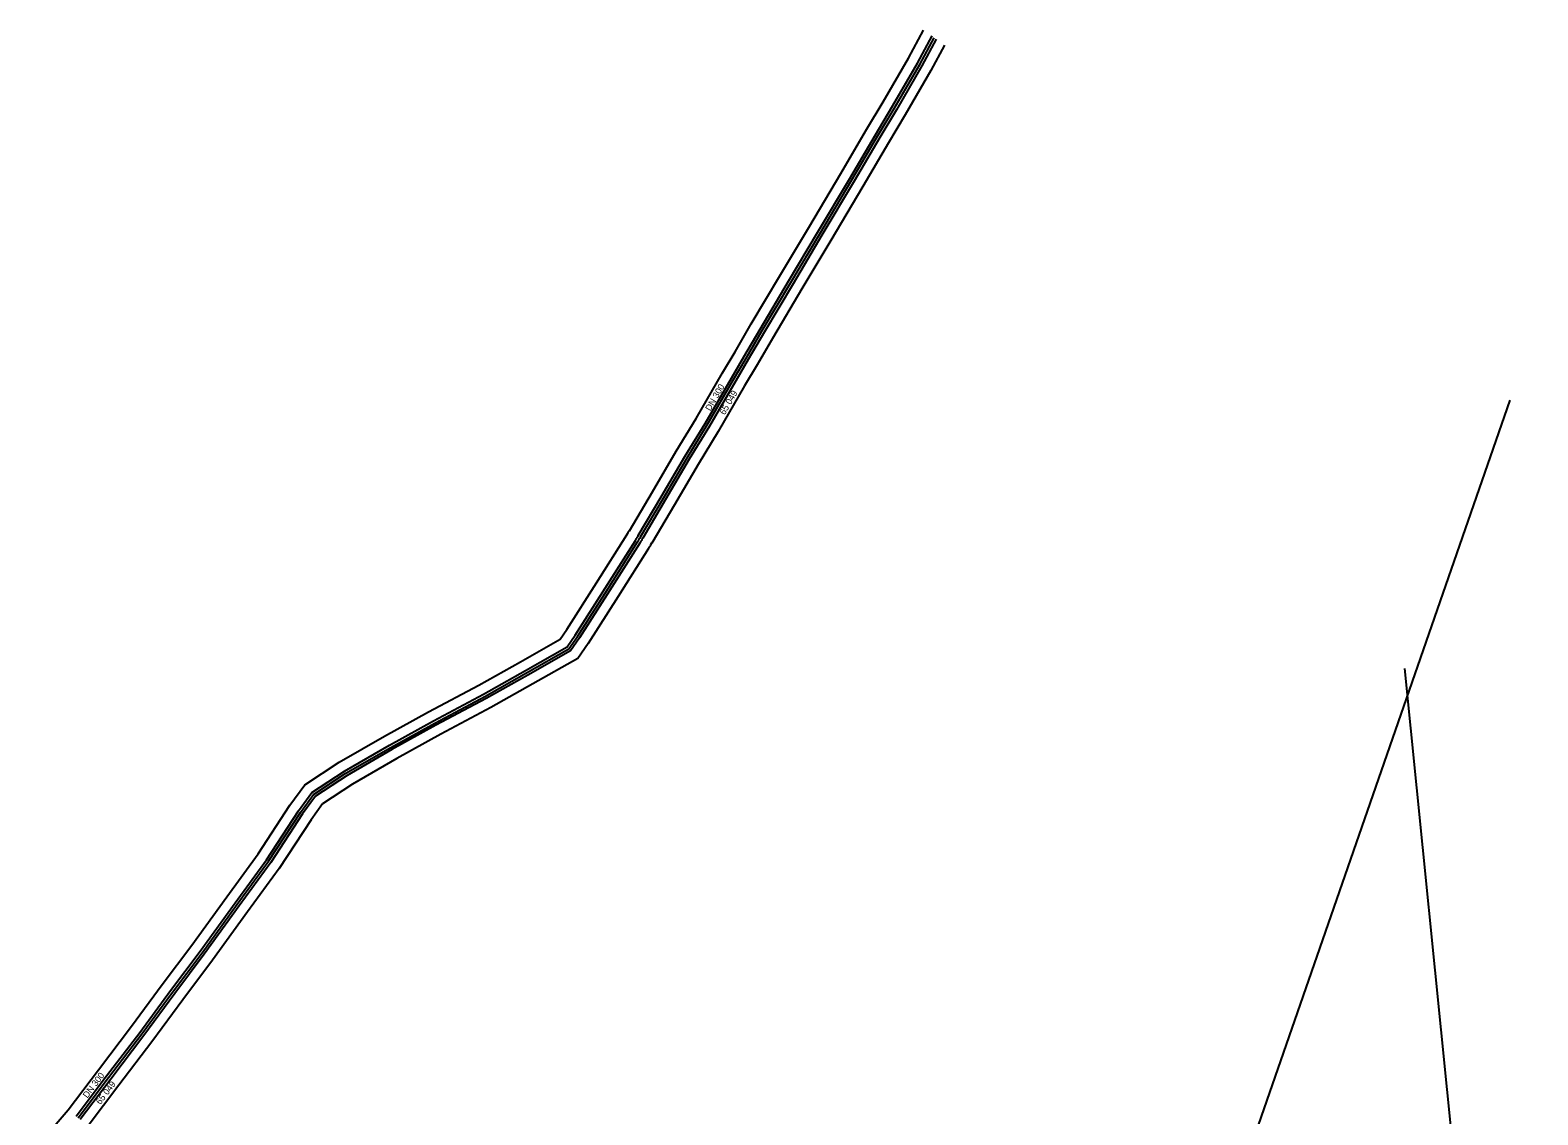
# Model space of a CAD drawing. Extents: x -546883 to -534032, y -1096714 to -1090569.
# Drawn here: x -542860 to -540504, y -1092586 to -1090891 of the extents above; entities that cross this region are included whole.
import ezdxf

# ---------------------------------------------------------------- set-up
doc = ezdxf.new("R2010")
doc.units = 0
for name, color, linetype in [('Vrstva 22', 7, 'Continuous'), ('Vrstva 26', 7, 'Continuous'), ('Vrstva 3', 7, 'Continuous'), ('Vrstva 8', 7, 'Continuous')]:
    doc.layers.add(name, color=color, linetype=linetype)

msp = doc.modelspace()

# ---------------------------------------------------------------- linework, layer by layer
at = {"layer": 'Vrstva 22'}
for p, q in [((-541554.5, -1094369.3), (-540547.1, -1091469.5)), ((-540503.9, -1093950.2), (-540711.5, -1091888.4))]:
    msp.add_line(p, q, dxfattribs=at)
at = {"layer": 'Vrstva 26'}
msp.add_lwpolyline([(-542785.2, -1092590.2), (-542737.4, -1092527.2), (-542685.7, -1092459.3), (-542637.4, -1092393.8), (-542591.2, -1092332.3), (-542536.4, -1092256.6), (-542487.4, -1092189.3), (-542437.5, -1092113.2), (-542417, -1092085.1), (-542366.6, -1092052), (-542296.6, -1092011.6), (-542227.8, -1091973.6), (-542149.5, -1091932), (-542084.2, -1091895.2), (-542018.2, -1091857.7), (-542004.8, -1091838.4), (-541957.9, -1091765.3), (-541910.7, -1091690.5), (-541908.9, -1091687.5), (-541908.6, -1091687), (-541908.2, -1091686.3), (-541907.8, -1091685.6), (-541907.4, -1091685.1), (-541906.2, -1091683.1), (-541906.1, -1091682.8), (-541870.5, -1091622.5), (-541833.4, -1091559.4), (-541801.9, -1091508.1), (-541760.8, -1091437), (-541741.3, -1091403.8), (-541715.9, -1091360.5), (-541671.2, -1091285.4), (-541626.1, -1091209.7), (-541575.8, -1091125.4), (-541535.8, -1091057), (-541509.7, -1091013.7), (-541469.9, -1090944.9), (-541447.3, -1090903.2)], dxfattribs=at)
at = {"layer": 'Vrstva 3'}
for points in [[(-542860, -1092647.2), (-542800.8, -1092577.6), (-542753.3, -1092515.1), (-542701.7, -1092447.3), (-542653.5, -1092381.8), (-542607.3, -1092320.4), (-542552.6, -1092244.9), (-542503.8, -1092178), (-542454, -1092101.9), (-542431, -1092070.4), (-542377.1, -1092034.9), (-542306.4, -1091994.1), (-542237.3, -1091956), (-542159.1, -1091914.5), (-542094, -1091877.8), (-542032, -1091842.5), (-542021.4, -1091827.3), (-541974.8, -1091754.5), (-541927.7, -1091679.9), (-541926, -1091677.1), (-541925.7, -1091676.7), (-541925.3, -1091675.9), (-541924.8, -1091675.2), (-541924.5, -1091674.7), (-541923.7, -1091673.4), (-541923.6, -1091673.2), (-541887.7, -1091612.4), (-541850.6, -1091549.1), (-541819, -1091497.8), (-541778, -1091426.9), (-541758.5, -1091393.7), (-541733.1, -1091350.3), (-541688.4, -1091275.2), (-541643.3, -1091199.4), (-541593, -1091115.2), (-541553, -1091046.8), (-541526.9, -1091003.6), (-541487.4, -1090935.1), (-541463.7, -1090891.5)], [(-541430.9, -1090914.9), (-541452.5, -1090954.7), (-541492.5, -1091023.9), (-541518.6, -1091067.2), (-541558.6, -1091135.5), (-541609, -1091219.9), (-541654.1, -1091295.6), (-541698.6, -1091370.6), (-541724, -1091413.9), (-541743.5, -1091447.1), (-541784.7, -1091518.3), (-541816.3, -1091569.7), (-541853.2, -1091632.7), (-541888.6, -1091692.5), (-541888.8, -1091692.9), (-541890.4, -1091695.5), (-541890.7, -1091696), (-541891.1, -1091696.7), (-541891.4, -1091697.3), (-541891.8, -1091697.9), (-541893.8, -1091701.1), (-541941, -1091776), (-541988.1, -1091849.5), (-542004.4, -1091872.8), (-542074.3, -1091912.6), (-542139.9, -1091949.5), (-542218.2, -1091991.2), (-542286.8, -1092029), (-542356.1, -1092069), (-542403, -1092099.9), (-542421.1, -1092124.6), (-542470.9, -1092200.7), (-542520.2, -1092268.4), (-542575.1, -1092344.2), (-542621.4, -1092405.7), (-542669.7, -1092471.3), (-542721.4, -1092539.3), (-542769.6, -1092602.7)]]:
    msp.add_lwpolyline(points, dxfattribs=at)
at = {"layer": 'Vrstva 8'}
for points in [[(-542788.3, -1092587.7), (-542740.5, -1092524.7), (-542688.9, -1092456.9), (-542640.6, -1092391.4), (-542594.5, -1092329.9), (-542539.7, -1092254.3), (-542490.7, -1092187.1), (-542440.8, -1092111), (-542419.8, -1092082.2), (-542368.7, -1092048.6), (-542298.5, -1092008.1), (-542229.7, -1091970.1), (-542151.4, -1091928.5), (-542086.1, -1091891.7), (-542020.9, -1091854.6), (-542008.1, -1091836.2), (-541961.3, -1091763.1), (-541914.1, -1091688.4), (-541912.3, -1091685.4), (-541912, -1091684.9), (-541911.6, -1091684.2), (-541911.2, -1091683.5), (-541910.8, -1091683), (-541909.7, -1091681.2), (-541909.6, -1091680.9), (-541873.9, -1091620.5), (-541836.8, -1091557.4), (-541805.3, -1091506), (-541764.2, -1091435), (-541744.7, -1091401.7), (-541719.3, -1091358.4), (-541674.7, -1091283.4), (-541629.6, -1091207.6), (-541579.2, -1091123.3), (-541539.2, -1091054.9), (-541513.2, -1091011.7), (-541473.4, -1090943), (-541450.4, -1090900.5)], [(-541444.1, -1090905.7), (-541466.4, -1090946.9), (-541506.3, -1091015.8), (-541532.4, -1091059), (-541572.4, -1091127.4), (-541622.7, -1091211.7), (-541667.8, -1091287.5), (-541712.4, -1091362.5), (-541737.8, -1091405.8), (-541757.3, -1091439), (-541798.4, -1091510.1), (-541830, -1091561.5), (-541867, -1091624.6), (-541902.6, -1091684.8), (-541902.8, -1091685.1), (-541904, -1091687.2), (-541904.3, -1091687.7), (-541904.7, -1091688.4), (-541905.2, -1091689.1), (-541905.5, -1091689.6), (-541907.3, -1091692.6), (-541954.5, -1091767.4), (-542001.5, -1091840.6), (-542015.4, -1091860.7), (-542082.2, -1091898.6), (-542147.6, -1091935.5), (-542225.9, -1091977.1), (-542294.6, -1092015), (-542364.5, -1092055.4), (-542414.2, -1092088.1), (-542434.2, -1092115.5), (-542484.1, -1092191.6), (-542533.2, -1092259), (-542588, -1092334.7), (-542634.2, -1092396.1), (-542682.5, -1092461.7), (-542734.2, -1092529.6), (-542782.1, -1092592.7)]]:
    msp.add_lwpolyline(points, dxfattribs=at)

# ---------------------------------------------------------------- texts
at = {"layer": 'Vrstva 26'}
for s, rotation, p in [('DN 300', 59.947, (-541797.1, -1091487.1)), ('65 049', 59.947, (-541774.6, -1091493.2)), ('DN 300', 52.7855, (-542770.7, -1092560.3)), ('65 049', 52.7855, (-542750.3, -1092570.3))]:
    msp.add_text(s, height=10, rotation=rotation, dxfattribs=at).set_placement(p)

doc.saveas('drawing.dxf')
